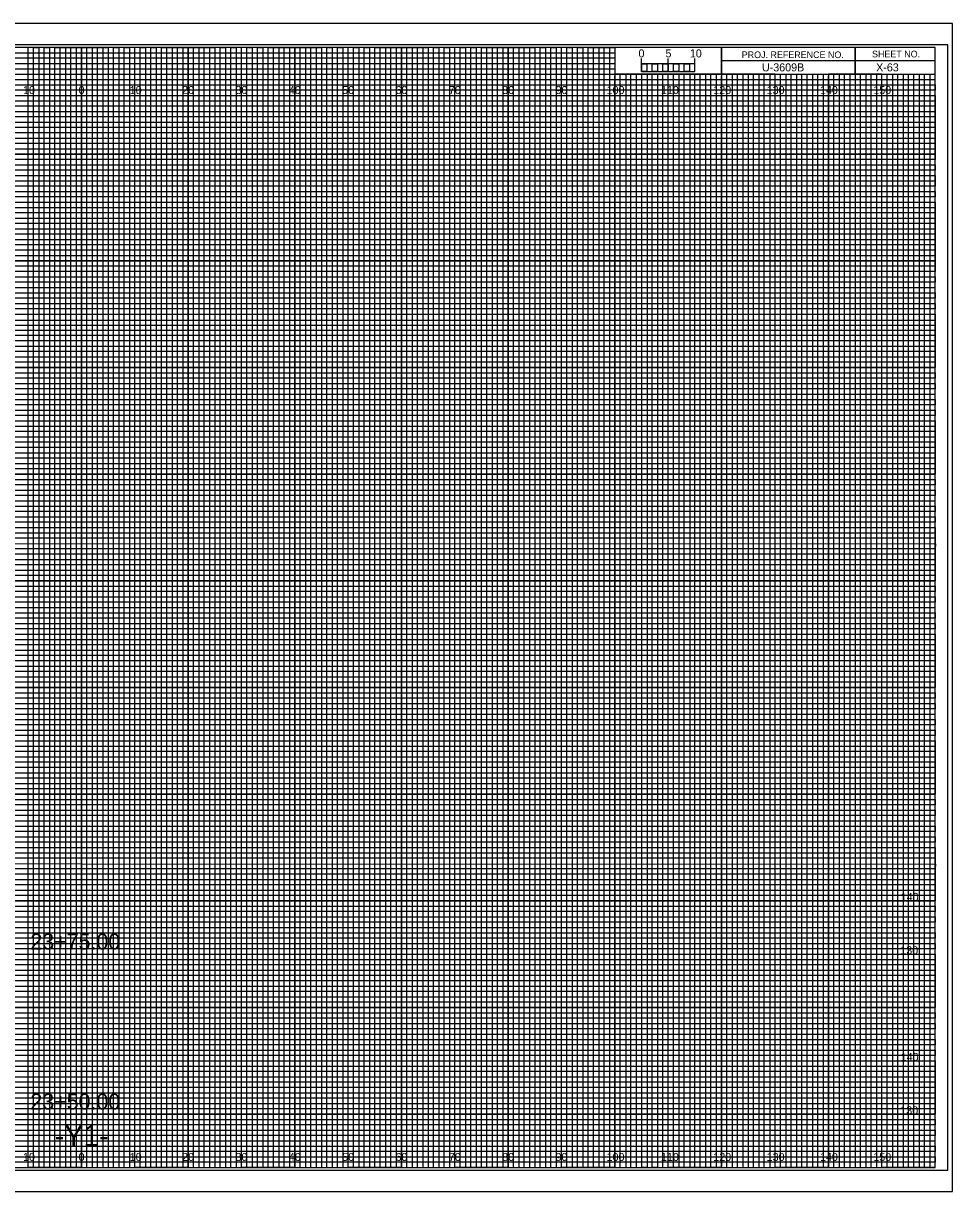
# Model space of a CAD drawing. Extents: x -13 to 323, y -5 to 2634.
# Drawn here: x 149.1 to 323.3, y 2415.5 to 2634.5 of the extents above; entities that cross this region are included whole.
import ezdxf

# ---------------------------------------------------------------- set-up
doc = ezdxf.new("R2010")
doc.units = 0
for name, color, linetype in [('Exist Cross Section Cell', 7, 'Continuous'), ('Exist XS Center Line Elevation Label', 7, 'Continuous'), ('Exist XS Ground Line', 7, 'Continuous'), ('Prop CMT Pvmt Course 1', 7, 'Continuous'), ('Prop CMT Pvmt Course 1 Wedge', 7, 'Continuous'), ('Prop CMT Pvmt Course 2', 7, 'Continuous'), ('Prop CMT Pvmt Course 2 Wedge', 7, 'Continuous'), ('Prop CMT Pvmt Course 3', 7, 'Continuous'), ('Prop CMT Pvmt Course 3 Wedge', 7, 'Continuous'), ('Prop CMT Pvmt Surface Shoulder', 7, 'Continuous'), ('Prop CMT Pvmt Wedge Surface 3', 7, 'Continuous'), ('Prop CMT Shld Paved Course 1', 7, 'Continuous'), ('Prop CMT Shld Paved Course 2', 7, 'Continuous'), ('Prop CMT Shld Paved Course 3', 7, 'Continuous'), ('Prop CMT Slope Grass', 7, 'Continuous'), ('Prop CMT Subgrade Earthwork', 7, 'Continuous'), ('Scratch_Level_0', 7, 'Continuous')]:
    doc.layers.add(name, color=color, linetype=linetype)

msp = doc.modelspace()

# ---------------------------------------------------------------- linework, layer by layer
at = {"layer": 'Exist XS Center Line Elevation Label'}
for points in [[(145, 2420), (155, 2420), (155, 2630), (165, 2630), (165, 2420), (175, 2420), (175, 2630), (185, 2630), (185, 2420), (195, 2420), (195, 2630), (205, 2630), (205, 2420), (215, 2420), (215, 2630), (225, 2630), (225, 2420), (235, 2420), (235, 2630), (245, 2630), (245, 2420), (255, 2420), (255, 2630), (259.93, 2630), (260, 2630), (260, 2625), (264.99, 2625), (264.99, 2420), (275, 2420), (275, 2625), (285, 2625), (285, 2420), (295, 2420), (295, 2625), (305, 2625), (305, 2420), (315, 2420), (315, 2625)], [(0, 2625), (275, 2625)], [(0, 2605), (320, 2605), (320, 2615), (0, 2615)], [(0, 2585), (320, 2585), (320, 2595), (0, 2595)], [(0, 2565), (320, 2565), (320, 2575), (0, 2575)], [(0, 2545), (320, 2545), (320, 2555), (0, 2555)], [(0, 2525), (320, 2525), (320, 2535), (0, 2535)], [(0, 2505), (320, 2505), (320, 2515), (0, 2515)], [(0, 2485), (320, 2485), (320, 2495), (0, 2495)], [(0, 2465), (320, 2465), (320, 2475), (0, 2475)], [(0, 2445), (320, 2445), (320, 2455), (0, 2455)], [(0, 2425), (320, 2425), (320, 2435), (0, 2435)]]:
    msp.add_lwpolyline(points, dxfattribs=at)
at = {"layer": 'Exist XS Ground Line'}
for p, q in [((150, 2630), (140, 2630)), ((150, 2420), (150, 2630)), ((170, 2630), (160, 2630)), ((160, 2630), (160, 2420)), ((170, 2420), (170, 2630)), ((190, 2630), (180, 2630)), ((180, 2630), (180, 2420)), ((190, 2420), (190, 2630)), ((210, 2630), (200, 2630)), ((200, 2630), (200, 2420)), ((210, 2420), (210, 2630)), ((230, 2630), (220, 2630)), ((220, 2630), (220, 2420)), ((230, 2420), (230, 2630)), ((250, 2630), (240, 2630)), ((240, 2630), (240, 2420)), ((250, 2420), (250, 2630)), ((260, 2630), (260, 2420)), ((270, 2420), (270, 2625)), ((290, 2625), (280, 2625)), ((280, 2625), (280, 2420)), ((290, 2420), (290, 2625)), ((310, 2625), (300, 2625)), ((300, 2625), (300, 2420)), ((310, 2420), (310, 2625)), ((160, 2420), (150, 2420)), ((180, 2420), (170, 2420)), ((200, 2420), (190, 2420)), ((220, 2420), (210, 2420)), ((240, 2420), (230, 2420)), ((260, 2420), (250, 2420)), ((280, 2420), (270, 2420)), ((300, 2420), (290, 2420)), ((320, 2420), (310, 2420)), ((320, 2420), (320, 2420))]:
    msp.add_line(p, q, dxfattribs=at)
for points in [[(0, 2620), (320, 2620), (320, 2610), (0, 2610)], [(0, 2600), (320, 2600), (320, 2590), (0, 2590)], [(0, 2580), (320, 2580), (320, 2570), (0, 2570)], [(0, 2560), (320, 2560), (320, 2550), (0, 2550)], [(0, 2540), (320, 2540), (320, 2530), (0, 2530)], [(0, 2520), (320, 2520), (320, 2510), (0, 2510)], [(0, 2500), (320, 2500), (320, 2490), (0, 2490)], [(0, 2480), (320, 2480), (320, 2470), (0, 2470)], [(0, 2460), (320, 2460), (320, 2450), (0, 2450)], [(0, 2440), (320, 2440), (320, 2430), (0, 2430)]]:
    msp.add_lwpolyline(points, dxfattribs=at)
at = {"layer": 'Prop CMT Pvmt Course 1'}
for p, q in [((265, 2625.49), (265, 2627.9)), ((265, 2626.9), (265, 2627.9)), ((270, 2625.49), (270, 2627.9)), ((275, 2625.49), (275, 2627.9)), ((275, 2626.9), (275, 2627.9))]:
    msp.add_line(p, q, dxfattribs=at)
for points in [[(275, 2626.9), (265, 2626.9), (265, 2625.49), (275, 2625.49)], [(265, 2626.9), (266, 2626.9), (266, 2625.49), (265, 2625.49)], [(267, 2626.9), (268, 2626.9), (268, 2625.49), (267, 2625.49)], [(269, 2626.9), (270, 2626.9), (270, 2625.49), (269, 2625.49)], [(271, 2626.9), (272, 2626.9), (272, 2625.49), (271, 2625.49)], [(273, 2626.9), (274, 2626.9), (274, 2625.49), (273, 2625.49)]]:
    msp.add_lwpolyline(points, close=True, dxfattribs=at)
at = {"layer": 'Prop CMT Pvmt Surface Shoulder'}
for p, q in [((267, 2625), (266.01, 2625)), ((266.01, 2625), (266.01, 2420)), ((267, 2420), (267, 2625)), ((269, 2625), (268, 2625)), ((268, 2625), (268, 2420)), ((269, 2420), (269, 2625)), ((266.01, 2420), (265, 2420)), ((268, 2420), (267, 2420))]:
    msp.add_line(p, q, dxfattribs=at)
for points in [[(150, 2420), (151, 2420), (151, 2630), (152, 2630), (152, 2420)], [(152, 2420), (153, 2420), (153, 2630), (154, 2630), (154, 2420)], [(155, 2420), (156, 2420), (156, 2630), (157, 2630), (157, 2420)], [(157, 2420), (158, 2420), (158, 2630), (159, 2630), (159, 2420)], [(160, 2420), (161, 2420), (161, 2630), (162, 2630), (162, 2420)], [(162, 2420), (163, 2420), (163, 2630), (164, 2630), (164, 2420)], [(165, 2420), (166, 2420), (166, 2630), (167, 2630), (167, 2420)], [(167, 2420), (168, 2420), (168, 2630), (169, 2630), (169, 2420)], [(170, 2420), (171, 2420), (171, 2630), (172, 2630), (172, 2420)], [(172, 2420), (173, 2420), (173, 2630), (174, 2630), (174, 2420)], [(175, 2420), (176, 2420), (176, 2630), (177, 2630), (177, 2420)], [(177, 2420), (178, 2420), (178, 2630), (179, 2630), (179, 2420)], [(180, 2420), (181, 2420), (181, 2630), (182, 2630), (182, 2420)], [(182, 2420), (183, 2420), (183, 2630), (184, 2630), (184, 2420)], [(185, 2420), (186, 2420), (186, 2630), (187, 2630), (187, 2420)], [(187, 2420), (188, 2420), (188, 2630), (189, 2630), (189, 2420)], [(190, 2420), (191, 2420), (191, 2630), (192, 2630), (192, 2420)], [(192, 2420), (193, 2420), (193, 2630), (194, 2630), (194, 2420)], [(195, 2420), (196, 2420), (196, 2630), (197, 2630), (197, 2420)], [(197, 2420), (198, 2420), (198, 2630), (199, 2630), (199, 2420)], [(200, 2420), (201, 2420), (201, 2630), (202, 2630), (202, 2420)], [(202, 2420), (203, 2420), (203, 2630), (204, 2630), (204, 2420)], [(205, 2420), (206, 2420), (206, 2630), (207, 2630), (207, 2420)], [(207, 2420), (208, 2420), (208, 2630), (209, 2630), (209, 2420)], [(210, 2420), (211, 2420), (211, 2630), (212, 2630), (212, 2420)], [(212, 2420), (213, 2420), (213, 2630), (214, 2630), (214, 2420)], [(215, 2420), (216, 2420), (216, 2630), (217, 2630), (217, 2420)], [(217, 2420), (218, 2420), (218, 2630), (219, 2630), (219, 2420)], [(220, 2420), (221, 2420), (221, 2630), (222, 2630), (222, 2420)], [(222, 2420), (223, 2420), (223, 2630), (224, 2630), (224, 2420)], [(225, 2420), (226, 2420), (226, 2630), (227, 2630), (227, 2420)], [(227, 2420), (228, 2420), (228, 2630), (229, 2630), (229, 2420)], [(230, 2420), (231, 2420), (231, 2630), (232, 2630), (232, 2420)], [(232, 2420), (233, 2420), (233, 2630), (234, 2630), (234, 2420)], [(235, 2420), (236, 2420), (236, 2630), (237, 2630), (237, 2420)], [(237, 2420), (238, 2420), (238, 2630), (239, 2630), (239, 2420)], [(240, 2420), (241, 2420), (241, 2630), (242, 2630), (242, 2420)], [(242, 2420), (243, 2420), (243, 2630), (244, 2630), (244, 2420)], [(245, 2420), (246, 2420), (246, 2630), (247, 2630), (247, 2420)], [(247, 2420), (248, 2420), (248, 2630), (249, 2630), (249, 2420)], [(250, 2420), (251, 2420), (251, 2630), (252, 2630), (252, 2420)], [(252, 2420), (253, 2420), (253, 2630), (254, 2630), (254, 2420)], [(255, 2420), (256, 2420), (256, 2630), (257, 2630), (257, 2420)], [(257, 2420), (258, 2420), (258, 2630), (259, 2630), (259, 2420)], [(260, 2420), (261, 2420), (261, 2625), (262.02, 2625), (262.02, 2420)], [(262, 2420), (263, 2420), (263, 2625), (263.99, 2625), (263.99, 2420)], [(270, 2420), (270.98, 2420), (270.98, 2625), (272, 2625), (272, 2420)], [(272, 2420), (273, 2420), (273, 2625), (274.05, 2625), (274.05, 2420)], [(275, 2420), (276, 2420), (276, 2625), (277, 2625), (277, 2420)], [(277, 2420), (278, 2420), (278, 2625), (279, 2625), (279, 2420)], [(280, 2420), (281, 2420), (281, 2625), (282, 2625), (282, 2420)], [(282, 2420), (283, 2420), (283, 2625), (284, 2625), (284, 2420)], [(285, 2420), (286, 2420), (286, 2625), (287, 2625), (287, 2420)], [(287, 2420), (288, 2420), (288, 2625), (289, 2625), (289, 2420)], [(290, 2420), (291, 2420), (291, 2625), (292, 2625), (292, 2420)], [(292, 2420), (293, 2420), (293, 2625), (294, 2625), (294, 2420)], [(295, 2420), (296, 2420), (296, 2625), (297, 2625), (297, 2420)], [(297, 2420), (298, 2420), (298, 2625), (299, 2625), (299, 2420)], [(300, 2420), (301, 2420), (301, 2625), (302, 2625), (302, 2420)], [(302, 2420), (303, 2420), (303, 2625), (304, 2625), (304, 2420)], [(305, 2420), (306, 2420), (306, 2625), (307, 2625), (307, 2420)], [(307, 2420), (308, 2420), (308, 2625), (309, 2625), (309, 2420)], [(310, 2420), (311, 2420), (311, 2625), (312, 2625), (312, 2420)], [(312, 2420), (313, 2420), (313, 2625), (314, 2625), (314, 2420)], [(315, 2420), (316, 2420), (316, 2625), (317, 2625), (317, 2420)], [(317, 2420), (318, 2420), (318, 2625), (319, 2625), (319, 2420)]]:
    msp.add_lwpolyline(points, dxfattribs=at)
at = {"layer": 'Prop CMT Pvmt Wedge Surface 3'}
for p, q in [((305, 2630), (305, 2625)), ((305, 2625), (305, 2630)), ((280, 2627.5), (280, 2625)), ((320, 2627.49), (280, 2627.49)), ((280, 2625), (320, 2625))]:
    msp.add_line(p, q, dxfattribs=at)
for points in [[(320, 2630), (0, 2630), (0, 2420), (320, 2420)], [(280, 2630), (260, 2630), (260, 2625.03), (280, 2625.03)], [(320, 2630), (280, 2630), (280, 2625), (320, 2625)]]:
    msp.add_lwpolyline(points, close=True, dxfattribs=at)
at = {"layer": 'Prop CMT Shld Paved Course 1'}
for p, q in [((150, 2420), (150, 2630)), ((160, 2420), (160, 2630)), ((170, 2420), (170, 2630)), ((180, 2420), (180, 2630)), ((190, 2420), (190, 2630)), ((200, 2420), (200, 2630)), ((210, 2420), (210, 2630)), ((220, 2420), (220, 2630)), ((230, 2420), (230, 2630)), ((240, 2420), (240, 2630)), ((250, 2420), (250, 2630)), ((260, 2420), (260, 2624.69)), ((270, 2420), (270, 2624.69)), ((280, 2420), (280, 2624.69)), ((290, 2420), (290, 2624.69)), ((300, 2420), (300, 2624.69)), ((310, 2420), (310, 2624.69)), ((0, 2620), (320, 2620)), ((0, 2610), (320, 2610)), ((0, 2600), (320, 2600)), ((0, 2590), (320, 2590)), ((0, 2580), (320, 2580)), ((0, 2570), (320, 2570)), ((0, 2560), (320, 2560)), ((0, 2550), (320, 2550)), ((0, 2540), (320, 2540)), ((0, 2530), (320, 2530)), ((0, 2520), (320, 2520)), ((0, 2510), (320, 2510)), ((0, 2500), (320, 2500)), ((0, 2490), (320, 2490)), ((0, 2480), (320, 2480)), ((0, 2470), (320, 2470)), ((0, 2460), (320, 2460)), ((0, 2450), (320, 2450)), ((0, 2440), (320, 2440)), ((0, 2430), (320, 2430))]:
    msp.add_line(p, q, dxfattribs=at)
at = {"layer": 'Prop CMT Shld Paved Course 2'}
for p, q in [((323.3, 2634.5), (-13.4, 2634.5)), ((-13.4, 2415.5), (323.3, 2415.5))]:
    msp.add_line(p, q, dxfattribs=at)
at = {"layer": 'Prop CMT Slope Grass'}
msp.add_lwpolyline([(-10.8, 2419.5), (322.4, 2419.5), (322.4, 2630.5), (-10.8, 2630.5)], close=True, dxfattribs=at)
at = {"layer": 'Prop CMT Subgrade Earthwork'}
msp.add_lwpolyline([(-13.4, 2415.5), (323.3, 2415.5), (323.3, 2634.5), (-13.4, 2634.5)], close=True, dxfattribs=at)
at = {"layer": 'Scratch_Level_0'}
for p, q in [((0, 2629), (260, 2629)), ((260, 2629), (260, 2627.98)), ((260, 2627.98), (0, 2627.98)), ((0, 2627), (260, 2627)), ((260, 2625.89), (0, 2625.89)), ((260, 2627), (260, 2625.89)), ((0, 2624), (320, 2624))]:
    msp.add_line(p, q, dxfattribs=at)
for points in [[(0, 2623), (270, 2623), (320, 2623), (320, 2622), (0, 2622)], [(0, 2621), (320, 2621), (320, 2619), (0, 2619)], [(0, 2618), (320, 2618), (320, 2617), (0, 2616.98)], [(0, 2616), (320, 2616), (320, 2614), (0, 2614)], [(0, 2613), (320, 2613), (320, 2612), (0, 2612)], [(0, 2611), (320, 2611), (320, 2609), (0, 2609)], [(0, 2608), (320, 2608), (320, 2607), (0, 2607)], [(0, 2606), (320, 2606), (320, 2604), (0, 2604)], [(0, 2603), (320, 2603), (320, 2602), (0, 2602)], [(0, 2601), (320, 2601), (320, 2599), (0, 2599)], [(0, 2598), (320, 2598), (320, 2597), (0, 2597)], [(0, 2596), (320, 2596), (320, 2593.95), (320, 2593), (320, 2592), (0, 2592)], [(0, 2594), (320, 2594), (320, 2593), (0, 2593)], [(0, 2591), (320, 2591), (320, 2589), (0, 2589.03)], [(0, 2589.03), (320, 2589), (320, 2588), (0, 2588)], [(0, 2587), (320, 2587), (320, 2586), (0, 2586)], [(0, 2584), (320, 2584), (320, 2583), (0, 2583)], [(0, 2582), (320, 2582), (320, 2581), (0, 2581)], [(-0.07, 2578.89), (320, 2578.89), (320, 2577.88), (-0.07, 2577.88)], [(0, 2577), (320, 2577), (320, 2576), (0, 2576)], [(0, 2574), (320, 2574), (320, 2573), (0, 2573)], [(0, 2572), (320, 2572), (320, 2571), (0, 2571)], [(0, 2569), (320, 2569), (320, 2568), (0, 2568)], [(0, 2567), (320, 2567), (320, 2566), (0, 2566)], [(0, 2564), (320, 2564), (320, 2563), (0, 2563)], [(0, 2562), (320, 2562), (320, 2561), (0, 2561)], [(0, 2559), (320, 2559), (319.99, 2557.98), (0, 2558)], [(0, 2557), (320, 2557), (320, 2556), (0, 2556)], [(0, 2554), (320, 2554), (320, 2553), (0, 2553)], [(0, 2552), (320, 2552), (320, 2551), (0, 2551)], [(0, 2549), (320, 2549), (320, 2548), (0, 2548)], [(0, 2547), (320, 2547), (320, 2546), (0, 2546)], [(0, 2544), (320, 2544), (320, 2543), (0, 2543)], [(0, 2542), (320, 2542), (320, 2541), (0, 2541)], [(0, 2539), (320, 2539), (320, 2538), (0, 2538)], [(0, 2536.99), (320.07, 2536.91), (320, 2536), (0, 2536)], [(0, 2534), (320, 2534), (320, 2533), (0, 2533)], [(0, 2532), (320, 2532), (320, 2531), (0, 2531)], [(0, 2529), (320, 2529), (320, 2528), (0, 2528)], [(0, 2527), (320, 2527), (320, 2526), (0, 2526)], [(0, 2524), (320, 2524), (320, 2523), (0, 2523)], [(0, 2522), (320, 2522), (320, 2521), (0, 2521)], [(0, 2519), (320, 2519), (320, 2518), (0, 2518)], [(0, 2517), (320, 2517), (320, 2516), (0, 2516)], [(0, 2514), (320, 2514), (320, 2513), (0, 2513)], [(0, 2512), (320, 2512), (320, 2511), (0, 2511)], [(0, 2509), (320, 2509), (320, 2508), (0, 2508)], [(0, 2507), (320, 2507), (320, 2506), (0, 2506)], [(0, 2504), (320, 2504), (320, 2503), (0, 2503)], [(0, 2502), (320, 2502), (320, 2501), (0, 2501)], [(0, 2499), (320, 2499), (319.99, 2497.98), (0, 2498)], [(0, 2497), (320, 2497), (320, 2496), (0, 2496)], [(0, 2494), (320, 2494), (320, 2493), (0, 2493)], [(0, 2492), (320, 2492), (320, 2491), (0, 2491)], [(0, 2489), (320, 2489), (320, 2488), (0, 2488)], [(0, 2487), (320, 2487), (320, 2486), (0, 2486)], [(0, 2484), (320, 2484), (320, 2483), (0, 2483)], [(0, 2482), (320, 2482), (320, 2481), (0, 2481)], [(0, 2479), (320, 2479), (320, 2478), (0, 2478)], [(0, 2476.99), (320.07, 2476.91), (320, 2476), (0, 2476)], [(0, 2474), (320, 2474), (320, 2473), (0, 2473)], [(0, 2472), (320, 2472), (320, 2471), (0, 2471)], [(0, 2469), (320, 2469), (320, 2468), (0, 2468)], [(0, 2467), (320, 2467), (320, 2466), (0, 2466)], [(0, 2464), (320, 2464), (320, 2463), (0, 2463)], [(0, 2462), (320, 2462), (320, 2461), (0, 2461)], [(0, 2459), (320, 2459), (320, 2458), (0, 2458)], [(0, 2457), (320, 2457), (320, 2456), (0, 2456)], [(0, 2454), (320, 2454), (320, 2453), (0, 2453)], [(0, 2452), (320, 2452), (320, 2451), (0, 2451)], [(0, 2449), (320, 2449), (320, 2448), (0, 2448)], [(0, 2447), (320, 2447), (320, 2446), (0, 2446)], [(0, 2444), (320, 2444), (320, 2443), (0, 2443)], [(0, 2442), (320, 2442), (320, 2441), (0, 2441)], [(0, 2439), (320, 2439), (320, 2438), (0, 2438)], [(0, 2437), (320, 2437), (320, 2436), (0, 2436)], [(0, 2434), (320, 2434), (320, 2433), (0, 2433)], [(0, 2432), (320, 2432), (320, 2431), (0, 2431)], [(0, 2429), (320, 2429), (320, 2428), (0, 2428)], [(0, 2427), (320, 2427), (320, 2426), (0, 2426)], [(0, 2424), (320, 2424), (320, 2423), (0, 2423)], [(0, 2422), (320, 2422), (320, 2421), (0, 2421)]]:
    msp.add_lwpolyline(points, dxfattribs=at)

# ---------------------------------------------------------------- texts
at = {"layer": 'Exist Cross Section Cell'}
for s, p in [('10', (149.04, 2621.25)), ('0', (159.45, 2621.25)), ('0', (159.45, 2621.25)), ('10', (169.04, 2621.25)), ('20', (178.86, 2621.25)), ('30', (188.86, 2621.25)), ('40', (198.86, 2621.25)), ('50', (208.86, 2621.25)), ('60', (218.86, 2621.25)), ('70', (228.86, 2621.25)), ('80', (238.86, 2621.25)), ('90', (248.86, 2621.25)), ('100', (258.44, 2621.25)), ('110', (268.62, 2621.25)), ('120', (278.44, 2621.25)), ('130', (288.44, 2621.25)), ('140', (298.44, 2621.25)), ('150', (308.44, 2621.25)), ('10', (149.04, 2421.25)), ('0', (159.45, 2421.25)), ('0', (159.45, 2421.25)), ('10', (169.04, 2421.25)), ('20', (178.86, 2421.25)), ('30', (188.86, 2421.25)), ('40', (198.86, 2421.25)), ('50', (208.86, 2421.25)), ('60', (218.86, 2421.25)), ('70', (228.86, 2421.25)), ('80', (238.86, 2421.25)), ('90', (248.86, 2421.25)), ('100', (258.44, 2421.25)), ('110', (268.62, 2421.25)), ('120', (278.44, 2421.25)), ('130', (288.44, 2421.25)), ('140', (298.44, 2421.25)), ('150', (308.44, 2421.25))]:
    msp.add_text(s, height=1.5, dxfattribs=at).set_placement(p)
at = {"layer": 'Prop CMT Pvmt Course 1'}
msp.add_text('0', height=1.5, dxfattribs=at).set_placement((264.41, 2628.12))
at = {"layer": 'Prop CMT Pvmt Course 1 Wedge'}
msp.add_text('U-3609B', height=1.5, dxfattribs=at).set_placement((287.56, 2625.5))
at = {"layer": 'Prop CMT Pvmt Course 2'}
for s, p in [('23+75.00', (150.41, 2460.88)), ('23+50.00', (150.41, 2430.88))]:
    msp.add_text(s, height=3, dxfattribs=at).set_placement(p)
at = {"layer": 'Prop CMT Pvmt Course 2 Wedge'}
msp.add_text('-Y1-', height=4, dxfattribs=at).set_placement((154.99, 2424))
at = {"layer": 'Prop CMT Pvmt Course 3'}
msp.add_text('X-63', height=1.5, dxfattribs=at).set_placement((308.96, 2625.5))
at = {"layer": 'Prop CMT Pvmt Course 3 Wedge'}
for s, p in [('5', (269.47, 2628.12)), ('10', (274.04, 2628.12))]:
    msp.add_text(s, height=1.5, dxfattribs=at).set_placement(p)
at = {"layer": 'Prop CMT Pvmt Wedge Surface 3'}
for s, p in [('PROJ. REFERENCE NO.', (283.77, 2627.99)), ('SHEET NO.', (308.19, 2628.12))]:
    msp.add_text(s, height=1.25, dxfattribs=at).set_placement(p)
at = {"layer": 'Prop CMT Shld Paved Course 3'}
for s, p in [('140', (313.57, 2470)), ('130', (313.49, 2460)), ('140', (313.57, 2440)), ('130', (313.49, 2430))]:
    msp.add_text(s, height=1.5, dxfattribs=at).set_placement(p)

doc.saveas('drawing.dxf')
